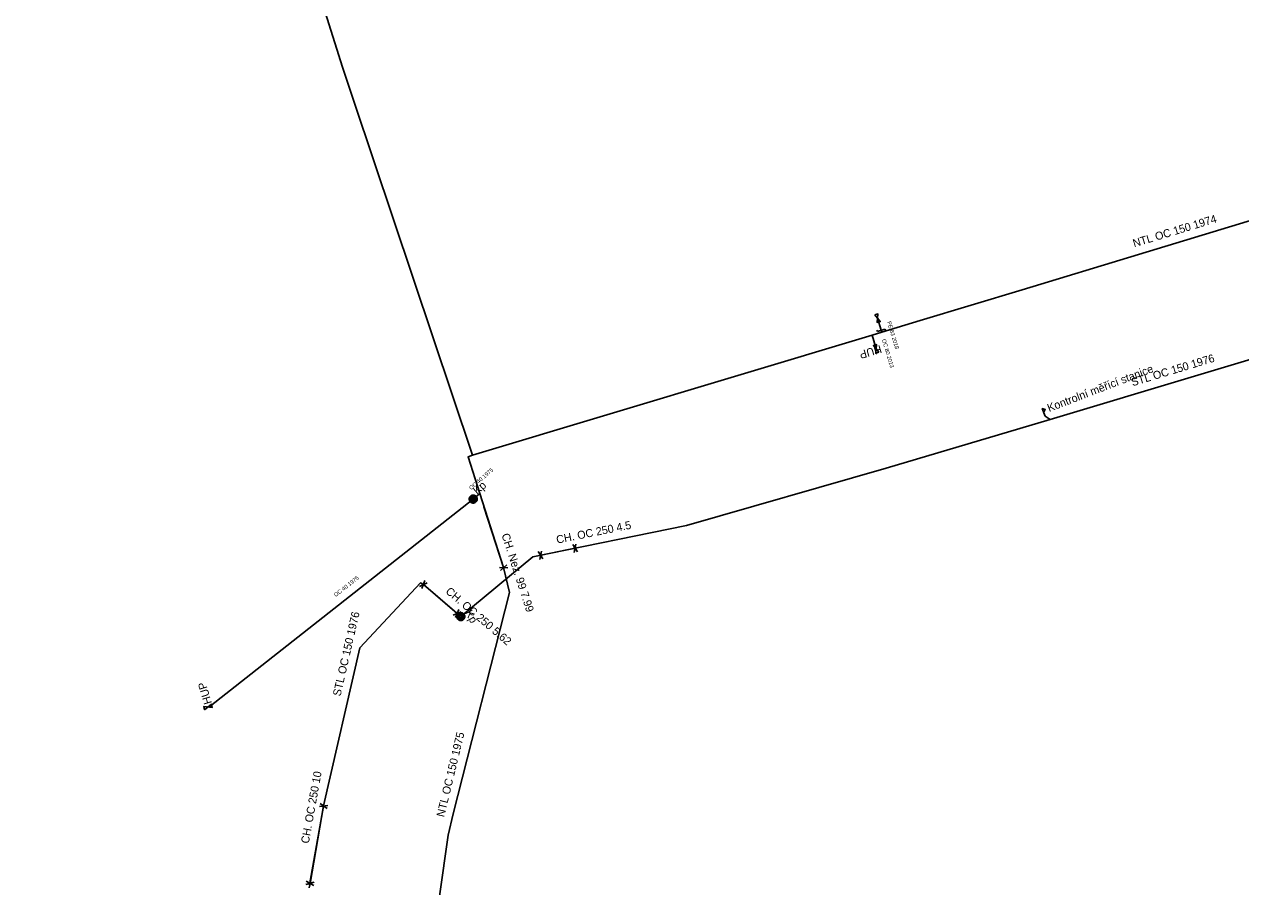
# Model space of a CAD drawing. Extents: x -743325 to -742825, y -1051501 to -1050981.
# Drawn here: x -743127 to -742975, y -1051218.8 to -1051110.9 of the extents above; entities that cross this region are included whole.
import ezdxf

# ---------------------------------------------------------------- set-up
doc = ezdxf.new("R2010")
doc.units = 0
for name, color, linetype in [('Kabel PKO', 7, 'Continuous'), ('NT Kapák - provoz_popis', 7, 'Continuous'), ('NT OP Chráni_ka - provoz', 7, 'Continuous'), ('NT Úsek p_ípojky - provoz', 7, 'Continuous'), ('NT Úsek plynovodu - provoz', 7, 'Continuous'), ('NT_HUP_24_popis', 7, 'Continuous'), ('ST Kapák - provoz_popis', 7, 'Continuous'), ('ST OP Chráni_ka - provoz', 7, 'Continuous'), ('ST Úsek plynovodu - provoz', 7, 'Continuous'), ('Vrstva 1', 7, 'Continuous'), ('Vrstva 5', 7, 'Continuous'), ('Za_ízení PKO - provoz_popis', 7, 'Continuous')]:
    doc.layers.add(name, color=color, linetype=linetype)

msp = doc.modelspace()

# ---------------------------------------------------------------- linework, layer by layer
at = {"layer": 'Kabel PKO'}
msp.add_lwpolyline([(-742998.83, -1051160.33), (-742999.45, -1051159.92)], dxfattribs=at)
at = {"layer": 'NT OP Chráni_ka - provoz'}
msp.add_lwpolyline([(-743067.1, -1051178.87), (-743069.55, -1051171.26)], dxfattribs=at)
at = {"layer": 'NT Úsek p_ípojky - provoz'}
for points in [[(-743019.94, -1051149.19), (-743020.39, -1051147.69)], [(-743019.86, -1051149.44), (-743019.94, -1051149.19)], [(-743021.06, -1051149.81), (-743020.55, -1051151.52)], [(-743070.9, -1051170.29), (-743103.74, -1051196.2), (-743104.03, -1051196.29)], [(-743070.08, -1051169.59), (-743070.9, -1051170.29)]]:
    msp.add_lwpolyline(points, dxfattribs=at)
at = {"layer": 'NT Úsek plynovodu - provoz'}
for points in [[(-743070.97, -1051164.82), (-743085.82, -1051120.54), (-743087.22, -1051116.29), (-743096.84, -1051085.73), (-743098.06, -1051081.53), (-743107.07, -1051050.52), (-743108.17, -1051046.32), (-743117.24, -1051015.64), (-743124.08, -1050990.52), (-743126.97, -1050981.05)], [(-742905.2, -1051114.38), (-742907.71, -1051115.12), (-742933.01, -1051122.87), (-742942.73, -1051125.88), (-742950.11, -1051128.19), (-742960.77, -1051131.52), (-742966.82, -1051133.35), (-742966.83, -1051133.35), (-742968.17, -1051133.76), (-742987.77, -1051139.71), (-743002.3, -1051144.12), (-743015.04, -1051147.98), (-743019.86, -1051149.44), (-743021.06, -1051149.81), (-743070.97, -1051164.82)], [(-743070.97, -1051164.82), (-743071.53, -1051165.02), (-743070.08, -1051169.59), (-743067.1, -1051178.87), (-743066.36, -1051181.99), (-743073.4, -1051209.66), (-743074.04, -1051212.31), (-743075.12, -1051219.94), (-743074.63, -1051228.86), (-743073.1, -1051242.44), (-743069.65, -1051257.35)]]:
    msp.add_lwpolyline(points, dxfattribs=at)
at = {"layer": 'ST OP Chráni_ka - provoz'}
for points in [[(-743062.42, -1051177.3), (-743058.01, -1051176.41)], [(-743077.23, -1051180.92), (-743077.12, -1051180.98)], [(-743077.12, -1051180.98), (-743072.95, -1051184.56)], [(-743089.58, -1051208.68), (-743091.34, -1051218.51)]]:
    msp.add_lwpolyline(points, dxfattribs=at)
at = {"layer": 'ST Úsek plynovodu - provoz'}
for points in [[(-742902.36, -1051131.35), (-742943.88, -1051143.86), (-742998.83, -1051160.34), (-743019.29, -1051166.45), (-743044.23, -1051173.62), (-743063.43, -1051177.51), (-743072.45, -1051184.99)], [(-743072.45, -1051184.99), (-743072.91, -1051184.6), (-743077.12, -1051180.98), (-743077.49, -1051180.78), (-743085.06, -1051188.9), (-743089.58, -1051208.66), (-743091.27, -1051218.34), (-743091.38, -1051218.91)]]:
    msp.add_lwpolyline(points, dxfattribs=at)
at = {"layer": 'Vrstva 1'}
for p, q in [((-743020.41, -1051149.33), (-743020.46, -1051149.19)), ((-743019.46, -1051149.05), (-743020.41, -1051149.33)), ((-743019.46, -1051149.05), (-743019.41, -1051149.19)), ((-743062.18, -1051177.77), (-743062.77, -1051176.86)), ((-743062.57, -1051177.84), (-743062.38, -1051176.79)), ((-743057.88, -1051176.9), (-743058.47, -1051175.99)), ((-743058.28, -1051176.97), (-743058.08, -1051175.92)), ((-743067.5, -1051179.23), (-743066.69, -1051178.51)), ((-743067.63, -1051178.85), (-743066.56, -1051178.89)), ((-743076.63, -1051180.75), (-743077.6, -1051181.21)), ((-743076.92, -1051180.47), (-743077.31, -1051181.48)), ((-743072.42, -1051184.38), (-743073.4, -1051184.82)), ((-743072.7, -1051184.1), (-743073.11, -1051185.1)), ((-743090.11, -1051208.72), (-743089.04, -1051208.6)), ((-743090.01, -1051208.34), (-743089.15, -1051208.98)), ((-743091.75, -1051218.08), (-743090.8, -1051218.6)), ((-743091.8, -1051218.48), (-743090.75, -1051218.2))]:
    msp.add_line(p, q, dxfattribs=at)
for points in [[(-743020.72, -1051147.26), (-743020.34, -1051147.15), (-743020.44, -1051148.22), (-743020.05, -1051148.11), (-743020.72, -1051147.26)], [(-743020.22, -1051151.94), (-743020.6, -1051152.06), (-743020.5, -1051150.98), (-743020.89, -1051151.1), (-743020.22, -1051151.94)], [(-743104.45, -1051196.63), (-743104.56, -1051196.24), (-743103.49, -1051196.34), (-743103.61, -1051195.95), (-743104.45, -1051196.63)]]:
    msp.add_lwpolyline(points, dxfattribs=at)
for points in [[(-743071.24, -1051169.93), (-743071.21, -1051169.9), (-743071.17, -1051169.87), (-743071.13, -1051169.85), (-743071.08, -1051169.83), (-743071.03, -1051169.81), (-743070.99, -1051169.8), (-743070.94, -1051169.8), (-743070.89, -1051169.79), (-743070.84, -1051169.8), (-743070.79, -1051169.81), (-743070.74, -1051169.82), (-743070.7, -1051169.84), (-743070.65, -1051169.86), (-743070.61, -1051169.88), (-743070.57, -1051169.91), (-743070.54, -1051169.95), (-743070.5, -1051169.99), (-743070.48, -1051170.03), (-743070.45, -1051170.07), (-743070.43, -1051170.11), (-743070.42, -1051170.16), (-743070.41, -1051170.21), (-743070.4, -1051170.26), (-743070.4, -1051170.31), (-743070.4, -1051170.35), (-743070.41, -1051170.4), (-743070.42, -1051170.45), (-743070.44, -1051170.5), (-743070.46, -1051170.54), (-743070.49, -1051170.58), (-743070.52, -1051170.62), (-743070.55, -1051170.66), (-743070.59, -1051170.69), (-743070.63, -1051170.72), (-743070.67, -1051170.74), (-743070.72, -1051170.76), (-743070.76, -1051170.78), (-743070.81, -1051170.79), (-743070.86, -1051170.79), (-743070.91, -1051170.8), (-743070.96, -1051170.79), (-743071.01, -1051170.78), (-743071.05, -1051170.77), (-743071.1, -1051170.75), (-743071.14, -1051170.73), (-743071.18, -1051170.71), (-743071.22, -1051170.68), (-743071.26, -1051170.64), (-743071.29, -1051170.6), (-743071.32, -1051170.56), (-743071.34, -1051170.52), (-743071.37, -1051170.48), (-743071.38, -1051170.43), (-743071.39, -1051170.38), (-743071.4, -1051170.33), (-743071.4, -1051170.28), (-743071.39, -1051170.24), (-743071.39, -1051170.19), (-743071.37, -1051170.14), (-743071.36, -1051170.09), (-743071.33, -1051170.05), (-743071.31, -1051170.01), (-743071.28, -1051169.97)], [(-743071.15, -1051170.54), (-743071.17, -1051170.51), (-743071.19, -1051170.48), (-743071.21, -1051170.45), (-743071.22, -1051170.42), (-743071.24, -1051170.39), (-743071.24, -1051170.36), (-743071.25, -1051170.32), (-743071.25, -1051170.29), (-743071.25, -1051170.25), (-743071.24, -1051170.22), (-743071.23, -1051170.19), (-743071.22, -1051170.15), (-743071.2, -1051170.12), (-743071.19, -1051170.09), (-743071.16, -1051170.07), (-743071.14, -1051170.04), (-743071.11, -1051170.02), (-743071.09, -1051170), (-743071.06, -1051169.98), (-743071.03, -1051169.97), (-743070.99, -1051169.96), (-743070.96, -1051169.95), (-743070.93, -1051169.95), (-743070.89, -1051169.94), (-743070.86, -1051169.95), (-743070.82, -1051169.95), (-743070.79, -1051169.96), (-743070.76, -1051169.97), (-743070.73, -1051169.99), (-743070.7, -1051170.01), (-743070.67, -1051170.03), (-743070.65, -1051170.05), (-743070.62, -1051170.08), (-743070.6, -1051170.11), (-743070.59, -1051170.14), (-743070.57, -1051170.17), (-743070.56, -1051170.2), (-743070.55, -1051170.23), (-743070.55, -1051170.27), (-743070.55, -1051170.3), (-743070.55, -1051170.34), (-743070.56, -1051170.37), (-743070.56, -1051170.4), (-743070.58, -1051170.44), (-743070.59, -1051170.47), (-743070.61, -1051170.5), (-743070.63, -1051170.52), (-743070.66, -1051170.55), (-743070.68, -1051170.57), (-743070.71, -1051170.59), (-743070.74, -1051170.61), (-743070.77, -1051170.62), (-743070.8, -1051170.63), (-743070.84, -1051170.64), (-743070.87, -1051170.64), (-743070.91, -1051170.65), (-743070.94, -1051170.64), (-743070.97, -1051170.64), (-743071.01, -1051170.63), (-743071.04, -1051170.62), (-743071.07, -1051170.6), (-743071.1, -1051170.58), (-743071.13, -1051170.56)], [(-743070.68, -1051170.09), (-743070.66, -1051170.11), (-743070.65, -1051170.13), (-743070.63, -1051170.16), (-743070.62, -1051170.19), (-743070.61, -1051170.21), (-743070.6, -1051170.24), (-743070.6, -1051170.27), (-743070.6, -1051170.3), (-743070.6, -1051170.33), (-743070.6, -1051170.36), (-743070.61, -1051170.39), (-743070.62, -1051170.42), (-743070.64, -1051170.44), (-743070.65, -1051170.47), (-743070.67, -1051170.49), (-743070.69, -1051170.51), (-743070.71, -1051170.53), (-743070.74, -1051170.55), (-743070.76, -1051170.56), (-743070.79, -1051170.57), (-743070.82, -1051170.58), (-743070.85, -1051170.59), (-743070.87, -1051170.59), (-743070.9, -1051170.6), (-743070.93, -1051170.59), (-743070.96, -1051170.59), (-743070.99, -1051170.58), (-743071.02, -1051170.57), (-743071.05, -1051170.56), (-743071.07, -1051170.54), (-743071.09, -1051170.52), (-743071.11, -1051170.5), (-743071.13, -1051170.48), (-743071.15, -1051170.46), (-743071.17, -1051170.43), (-743071.18, -1051170.4), (-743071.19, -1051170.38), (-743071.19, -1051170.35), (-743071.2, -1051170.32), (-743071.2, -1051170.29), (-743071.2, -1051170.26), (-743071.19, -1051170.23), (-743071.18, -1051170.2), (-743071.17, -1051170.17), (-743071.16, -1051170.15), (-743071.14, -1051170.12), (-743071.13, -1051170.1), (-743071.11, -1051170.08), (-743071.08, -1051170.06), (-743071.06, -1051170.04), (-743071.03, -1051170.03), (-743071.01, -1051170.02), (-743070.98, -1051170.01), (-743070.95, -1051170), (-743070.92, -1051170), (-743070.89, -1051169.99), (-743070.86, -1051170), (-743070.83, -1051170), (-743070.81, -1051170.01), (-743070.78, -1051170.02), (-743070.75, -1051170.03), (-743070.73, -1051170.05), (-743070.7, -1051170.07)], [(-743070.79, -1051170.19), (-743070.78, -1051170.2), (-743070.77, -1051170.21), (-743070.76, -1051170.23), (-743070.76, -1051170.24), (-743070.75, -1051170.25), (-743070.75, -1051170.27), (-743070.75, -1051170.28), (-743070.75, -1051170.3), (-743070.75, -1051170.31), (-743070.75, -1051170.33), (-743070.76, -1051170.34), (-743070.76, -1051170.36), (-743070.77, -1051170.37), (-743070.78, -1051170.38), (-743070.78, -1051170.39), (-743070.79, -1051170.4), (-743070.81, -1051170.41), (-743070.82, -1051170.42), (-743070.83, -1051170.43), (-743070.84, -1051170.43), (-743070.86, -1051170.44), (-743070.87, -1051170.44), (-743070.89, -1051170.45), (-743070.9, -1051170.45), (-743070.92, -1051170.44), (-743070.93, -1051170.44), (-743070.94, -1051170.44), (-743070.96, -1051170.43), (-743070.97, -1051170.43), (-743070.98, -1051170.42), (-743071, -1051170.41), (-743071.01, -1051170.4), (-743071.02, -1051170.39), (-743071.02, -1051170.38), (-743071.03, -1051170.36), (-743071.04, -1051170.35), (-743071.04, -1051170.34), (-743071.05, -1051170.32), (-743071.05, -1051170.31), (-743071.05, -1051170.29), (-743071.05, -1051170.28), (-743071.05, -1051170.26), (-743071.04, -1051170.25), (-743071.04, -1051170.23), (-743071.03, -1051170.22), (-743071.02, -1051170.21), (-743071.01, -1051170.2), (-743071, -1051170.19), (-743070.99, -1051170.18), (-743070.98, -1051170.17), (-743070.97, -1051170.16), (-743070.95, -1051170.16), (-743070.94, -1051170.15), (-743070.92, -1051170.15), (-743070.91, -1051170.15), (-743070.89, -1051170.14), (-743070.88, -1051170.15), (-743070.87, -1051170.15), (-743070.85, -1051170.15), (-743070.84, -1051170.16), (-743070.83, -1051170.16), (-743070.81, -1051170.17), (-743070.8, -1051170.18)], [(-743072.02, -1051184.73), (-743072, -1051184.77), (-743071.98, -1051184.82), (-743071.96, -1051184.86), (-743071.95, -1051184.91), (-743071.95, -1051184.96), (-743071.95, -1051185.01), (-743071.95, -1051185.06), (-743071.96, -1051185.11), (-743071.97, -1051185.15), (-743071.99, -1051185.2), (-743072.01, -1051185.24), (-743072.04, -1051185.28), (-743072.07, -1051185.32), (-743072.11, -1051185.36), (-743072.14, -1051185.39), (-743072.18, -1051185.42), (-743072.23, -1051185.44), (-743072.27, -1051185.46), (-743072.32, -1051185.48), (-743072.37, -1051185.49), (-743072.42, -1051185.49), (-743072.46, -1051185.49), (-743072.51, -1051185.49), (-743072.56, -1051185.48), (-743072.61, -1051185.47), (-743072.65, -1051185.45), (-743072.7, -1051185.43), (-743072.74, -1051185.4), (-743072.78, -1051185.37), (-743072.81, -1051185.33), (-743072.84, -1051185.3), (-743072.87, -1051185.26), (-743072.9, -1051185.21), (-743072.92, -1051185.17), (-743072.93, -1051185.12), (-743072.94, -1051185.07), (-743072.95, -1051185.02), (-743072.95, -1051184.98), (-743072.94, -1051184.93), (-743072.93, -1051184.88), (-743072.92, -1051184.83), (-743072.9, -1051184.79), (-743072.88, -1051184.74), (-743072.85, -1051184.7), (-743072.82, -1051184.66), (-743072.79, -1051184.63), (-743072.75, -1051184.6), (-743072.71, -1051184.57), (-743072.67, -1051184.54), (-743072.62, -1051184.52), (-743072.58, -1051184.51), (-743072.53, -1051184.5), (-743072.48, -1051184.49), (-743072.43, -1051184.49), (-743072.38, -1051184.5), (-743072.33, -1051184.51), (-743072.29, -1051184.52), (-743072.24, -1051184.54), (-743072.2, -1051184.56), (-743072.16, -1051184.59), (-743072.12, -1051184.62), (-743072.08, -1051184.65), (-743072.05, -1051184.69)], [(-743072.63, -1051184.7), (-743072.6, -1051184.68), (-743072.57, -1051184.66), (-743072.54, -1051184.65), (-743072.5, -1051184.65), (-743072.47, -1051184.64), (-743072.44, -1051184.64), (-743072.4, -1051184.65), (-743072.37, -1051184.65), (-743072.33, -1051184.66), (-743072.3, -1051184.67), (-743072.27, -1051184.69), (-743072.24, -1051184.71), (-743072.22, -1051184.73), (-743072.19, -1051184.75), (-743072.17, -1051184.78), (-743072.15, -1051184.81), (-743072.13, -1051184.84), (-743072.12, -1051184.87), (-743072.11, -1051184.9), (-743072.1, -1051184.94), (-743072.1, -1051184.97), (-743072.1, -1051185), (-743072.1, -1051185.04), (-743072.11, -1051185.07), (-743072.12, -1051185.11), (-743072.13, -1051185.14), (-743072.14, -1051185.17), (-743072.16, -1051185.2), (-743072.18, -1051185.22), (-743072.21, -1051185.25), (-743072.23, -1051185.27), (-743072.26, -1051185.29), (-743072.29, -1051185.31), (-743072.32, -1051185.32), (-743072.36, -1051185.33), (-743072.39, -1051185.34), (-743072.42, -1051185.34), (-743072.46, -1051185.34), (-743072.49, -1051185.34), (-743072.53, -1051185.33), (-743072.56, -1051185.32), (-743072.59, -1051185.31), (-743072.62, -1051185.3), (-743072.65, -1051185.28), (-743072.68, -1051185.26), (-743072.7, -1051185.23), (-743072.73, -1051185.21), (-743072.74, -1051185.18), (-743072.76, -1051185.15), (-743072.78, -1051185.12), (-743072.79, -1051185.08), (-743072.79, -1051185.05), (-743072.8, -1051185.02), (-743072.8, -1051184.98), (-743072.79, -1051184.95), (-743072.79, -1051184.91), (-743072.78, -1051184.88), (-743072.77, -1051184.85), (-743072.75, -1051184.82), (-743072.73, -1051184.79), (-743072.71, -1051184.76), (-743072.69, -1051184.74), (-743072.66, -1051184.71)], [(-743072.29, -1051185.25), (-743072.31, -1051185.26), (-743072.34, -1051185.27), (-743072.37, -1051185.28), (-743072.4, -1051185.29), (-743072.43, -1051185.29), (-743072.46, -1051185.29), (-743072.49, -1051185.29), (-743072.52, -1051185.29), (-743072.54, -1051185.28), (-743072.57, -1051185.27), (-743072.6, -1051185.25), (-743072.62, -1051185.24), (-743072.65, -1051185.22), (-743072.67, -1051185.2), (-743072.69, -1051185.18), (-743072.7, -1051185.15), (-743072.72, -1051185.13), (-743072.73, -1051185.1), (-743072.74, -1051185.07), (-743072.74, -1051185.04), (-743072.75, -1051185.01), (-743072.75, -1051184.98), (-743072.74, -1051184.95), (-743072.74, -1051184.92), (-743072.73, -1051184.9), (-743072.72, -1051184.87), (-743072.71, -1051184.84), (-743072.69, -1051184.82), (-743072.67, -1051184.79), (-743072.65, -1051184.77), (-743072.63, -1051184.75), (-743072.61, -1051184.74), (-743072.58, -1051184.72), (-743072.55, -1051184.71), (-743072.52, -1051184.7), (-743072.5, -1051184.7), (-743072.47, -1051184.69), (-743072.44, -1051184.69), (-743072.41, -1051184.69), (-743072.38, -1051184.7), (-743072.35, -1051184.71), (-743072.32, -1051184.72), (-743072.3, -1051184.73), (-743072.27, -1051184.75), (-743072.25, -1051184.77), (-743072.23, -1051184.79), (-743072.21, -1051184.81), (-743072.19, -1051184.83), (-743072.18, -1051184.86), (-743072.17, -1051184.89), (-743072.16, -1051184.92), (-743072.15, -1051184.94), (-743072.15, -1051184.97), (-743072.15, -1051185), (-743072.15, -1051185.03), (-743072.15, -1051185.06), (-743072.16, -1051185.09), (-743072.17, -1051185.12), (-743072.19, -1051185.14), (-743072.2, -1051185.17), (-743072.22, -1051185.19), (-743072.24, -1051185.21), (-743072.26, -1051185.23)], [(-743072.37, -1051185.12), (-743072.38, -1051185.13), (-743072.39, -1051185.13), (-743072.41, -1051185.14), (-743072.42, -1051185.14), (-743072.44, -1051185.14), (-743072.45, -1051185.14), (-743072.47, -1051185.14), (-743072.48, -1051185.14), (-743072.5, -1051185.14), (-743072.51, -1051185.13), (-743072.52, -1051185.12), (-743072.53, -1051185.11), (-743072.55, -1051185.11), (-743072.56, -1051185.1), (-743072.57, -1051185.08), (-743072.57, -1051185.07), (-743072.58, -1051185.06), (-743072.59, -1051185.05), (-743072.59, -1051185.03), (-743072.6, -1051185.02), (-743072.6, -1051185), (-743072.6, -1051184.99), (-743072.6, -1051184.97), (-743072.59, -1051184.96), (-743072.59, -1051184.94), (-743072.58, -1051184.93), (-743072.58, -1051184.92), (-743072.57, -1051184.91), (-743072.56, -1051184.89), (-743072.55, -1051184.88), (-743072.54, -1051184.87), (-743072.53, -1051184.87), (-743072.51, -1051184.86), (-743072.5, -1051184.85), (-743072.49, -1051184.85), (-743072.47, -1051184.84), (-743072.46, -1051184.84), (-743072.44, -1051184.84), (-743072.43, -1051184.84), (-743072.41, -1051184.85), (-743072.4, -1051184.85), (-743072.38, -1051184.86), (-743072.37, -1051184.86), (-743072.36, -1051184.87), (-743072.35, -1051184.88), (-743072.34, -1051184.89), (-743072.33, -1051184.9), (-743072.32, -1051184.91), (-743072.31, -1051184.93), (-743072.31, -1051184.94), (-743072.3, -1051184.95), (-743072.3, -1051184.97), (-743072.3, -1051184.98), (-743072.3, -1051185), (-743072.3, -1051185.01), (-743072.3, -1051185.03), (-743072.3, -1051185.04), (-743072.31, -1051185.05), (-743072.32, -1051185.07), (-743072.33, -1051185.08), (-743072.33, -1051185.09), (-743072.34, -1051185.1), (-743072.36, -1051185.11)]]:
    msp.add_lwpolyline(points, close=True, dxfattribs=at)
at = {"layer": 'Vrstva 5'}
msp.add_lwpolyline([(-742999.45, -1051159.92), (-742999.81, -1051158.98), (-742999.44, -1051159.11), (-742999.63, -1051159.45)], dxfattribs=at)

# ---------------------------------------------------------------- texts
at = {"layer": 'NT Kapák - provoz_popis'}
msp.add_text('Kp', height=1, rotation=41, dxfattribs=at).set_placement((-743070.4, -1051169.79))
at = {"layer": 'NT OP Chráni_ka - provoz'}
msp.add_text('CH. Nez. 99 7.99', height=1, rotation=287.8547, dxfattribs=at).set_placement((-743067.37, -1051174.76))
at = {"layer": 'NT Úsek p_ípojky - provoz'}
for s, rotation, p in [('PE 63 2018', 286.7516, (-743019.2, -1051148.15)), ('OC 80 2013', 286.6011, (-743019.85, -1051150.38)), ('OC 40 1975', 40.9707, (-743071.15, -1051169.19)), ('OC 40 1975', 38.2699, (-743088.06, -1051182.56))]:
    msp.add_text(s, height=0.5, rotation=rotation, dxfattribs=at).set_placement(p)
at = {"layer": 'NT Úsek plynovodu - provoz'}
for s, rotation, p in [('NTL OC 150 1974', 16.8705, (-742988.32, -1051138.83)), ('NTL OC 150 1975', 76.4021, (-743074.53, -1051210.12))]:
    msp.add_text(s, height=1, rotation=rotation, dxfattribs=at).set_placement(p)
at = {"layer": 'NT_HUP_24_popis'}
for rotation, p in [(196.6, (-743020.05, -1051151.02)), (106.86, (-743103.53, -1051195.79))]:
    msp.add_text('HUP', height=1, rotation=rotation, dxfattribs=at).set_placement(p)
at = {"layer": 'ST Kapák - provoz_popis'}
msp.add_text('Kp', height=1, rotation=299, dxfattribs=at).set_placement((-743071.95, -1051184.49))
at = {"layer": 'ST OP Chráni_ka - provoz'}
for s, rotation, p in [('CH. OC 250 4.5', 11.4449, (-743060.41, -1051175.88)), ('CH. OC 250 5.62', 319.2991, (-743074.43, -1051181.97)), ('CH. OC 250 10', 79.8023, (-743091.44, -1051213.42))]:
    msp.add_text(s, height=1, rotation=rotation, dxfattribs=at).set_placement(p)
at = {"layer": 'ST Úsek plynovodu - provoz'}
for rotation, p in [(16.6921, (-742988.52, -1051156.2)), (77.1248, (-743087.48, -1051195.01))]:
    msp.add_text('STL OC 150 1976', height=1, rotation=rotation, dxfattribs=at).set_placement(p)
at = {"layer": 'Za_ízení PKO - provoz_popis'}
msp.add_text('Kontrolní měřící stanice', height=1, rotation=21, dxfattribs=at).set_placement((-742998.95, -1051159.42))

doc.saveas('drawing.dxf')
